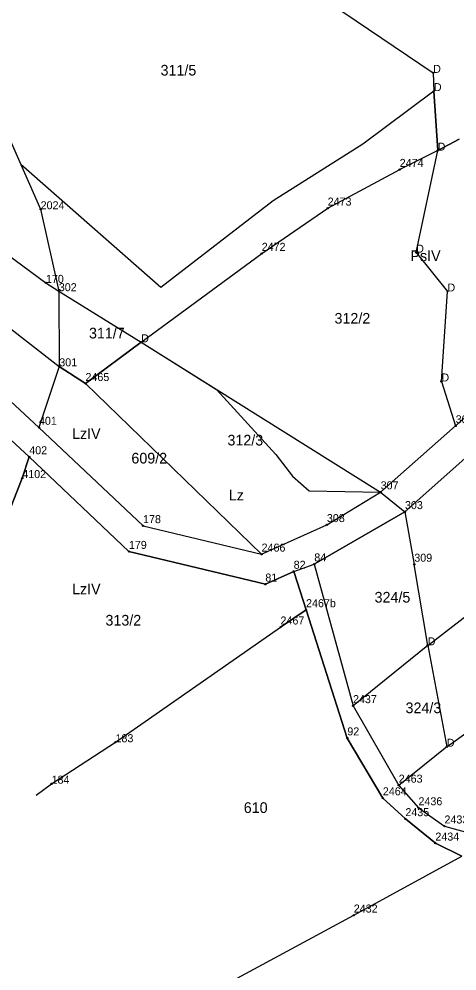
# Model space of a CAD drawing. Extents: x 7467189 to 7469366, y 5491487 to 5492734.
# Drawn here: x 7467655.3 to 7467716.9, y 5491813.8 to 5491947.6 of the extents above; entities that cross this region are included whole.
import ezdxf

# ---------------------------------------------------------------- set-up
doc = ezdxf.new("R2010")
doc.units = 0
for name, color, linetype in [('203-punkt graniczny', 7, 'Continuous'), ('203-punkt graniczny-Atr103', 7, 'Continuous'), ('209-oznaczenie konturu klasyfikacyjnego', 7, 'Continuous'), ('210-oznaczenie konturu użytku gruntowego', 7, 'Continuous'), ('211-numer działki ewidencyjnej', 7, 'Continuous'), ('217-kontur klasyfikacyjny', 7, 'Continuous'), ('218-kontur użytku gruntowego', 7, 'Continuous'), ('219-działka ewidencyjna', 7, 'Continuous')]:
    doc.layers.add(name, color=color, linetype=linetype)

# ---------------------------------------------------------------- blocks, each defined once
blk = doc.blocks.new('203')
blk.add_circle((0, 0), 0.09)

msp = doc.modelspace()

# ---------------------------------------------------------------- linework, layer by layer
at = {"layer": '217-kontur klasyfikacyjny'}
for points in [[(7467643.85, 5491953.77), (7467655.58, 5491927.15)], [(7467713.61, 5491937.44), (7467703.61, 5491929.97)], [(7467714.15, 5491929.08), (7467713.61, 5491937.44)], [(7467717.15, 5491930.69), (7467714.15, 5491929.08)], [(7467703.61, 5491929.97), (7467691.02, 5491922.04)], [(7467655.58, 5491927.15), (7467658.36, 5491920.84)], [(7467675.26, 5491909.83), (7467655.58, 5491927.15)], [(7467691.02, 5491922.04), (7467675.26, 5491909.83)], [(7467658.36, 5491920.84), (7467660.91, 5491909.33)], [(7467660.91, 5491909.33), (7467660.98, 5491898.77)], [(7467716.67, 5491890.39), (7467736.74, 5491908.19)], [(7467664.66, 5491896.34), (7467672.49, 5491902.15)], [(7467672.49, 5491902.15), (7467683.06, 5491895.54)], [(7467660.98, 5491898.77), (7467658.12, 5491890.18)], [(7467664.66, 5491896.34), (7467660.98, 5491898.77)], [(7467689.4, 5491872.36), (7467664.66, 5491896.34)], [(7467683.06, 5491895.54), (7467691.41, 5491886.39)], [(7467706.13, 5491881.11), (7467716.67, 5491890.39)], [(7467658.12, 5491890.18), (7467672.75, 5491876.36)], [(7467691.41, 5491886.39), (7467693.75, 5491883.34)], [(7467656.76, 5491886.05), (7467655.78, 5491883.07)], [(7467670.76, 5491872.75), (7467656.76, 5491886.05)], [(7467655.78, 5491883.07), (7467644.62, 5491854.62)], [(7467693.75, 5491883.34), (7467696.09, 5491881.3)], [(7467696.09, 5491881.3), (7467706.13, 5491881.11)], [(7467672.75, 5491876.36), (7467689.4, 5491872.36)], [(7467689.93, 5491868.15), (7467670.76, 5491872.75)], [(7467693.91, 5491869.96), (7467689.93, 5491868.15)], [(7467695.65, 5491864.56), (7467693.91, 5491869.96)], [(7467692.06, 5491862.13), (7467695.65, 5491864.56)], [(7467668.88, 5491845.96), (7467692.06, 5491862.13)], [(7467659.9, 5491840.13), (7467668.88, 5491845.96)], [(7467657.71, 5491838.52), (7467659.9, 5491840.13)]]:
    msp.add_lwpolyline(points, dxfattribs=at)
at = {"layer": '218-kontur użytku gruntowego'}
for points in [[(7467643.85, 5491953.77), (7467655.58, 5491927.15)], [(7467713.61, 5491937.44), (7467703.61, 5491929.97)], [(7467714.15, 5491929.08), (7467713.61, 5491937.44)], [(7467608.28, 5491936.44), (7467658.12, 5491890.18)], [(7467656.76, 5491886.05), (7467607.61, 5491931.54)], [(7467717.15, 5491930.69), (7467714.15, 5491929.08)], [(7467703.61, 5491929.97), (7467691.02, 5491922.04)], [(7467655.58, 5491927.15), (7467658.36, 5491920.84)], [(7467675.26, 5491909.83), (7467655.58, 5491927.15)], [(7467691.02, 5491922.04), (7467675.26, 5491909.83)], [(7467658.36, 5491920.84), (7467660.91, 5491909.33)], [(7467660.91, 5491909.33), (7467660.98, 5491898.77)], [(7467716.67, 5491890.39), (7467736.74, 5491908.19)], [(7467664.66, 5491896.34), (7467672.49, 5491902.15)], [(7467672.49, 5491902.15), (7467683.06, 5491895.54)], [(7467660.98, 5491898.77), (7467658.12, 5491890.18)], [(7467660.98, 5491898.77), (7467664.66, 5491896.34)], [(7467683.06, 5491895.54), (7467691.41, 5491886.39)], [(7467706.13, 5491881.11), (7467716.67, 5491890.39)], [(7467658.12, 5491890.18), (7467672.75, 5491876.36)], [(7467691.41, 5491886.39), (7467693.75, 5491883.34)], [(7467718.86, 5491886.6), (7467709.55, 5491878.34)], [(7467656.76, 5491886.05), (7467655.78, 5491883.07)], [(7467670.76, 5491872.75), (7467656.76, 5491886.05)], [(7467655.78, 5491883.07), (7467644.62, 5491854.62)], [(7467693.75, 5491883.34), (7467696.09, 5491881.3)], [(7467696.09, 5491881.3), (7467706.13, 5491881.11)], [(7467698.58, 5491876.52), (7467706.13, 5491881.11)], [(7467709.55, 5491878.34), (7467696.81, 5491870.98)], [(7467672.75, 5491876.36), (7467689.4, 5491872.36)], [(7467689.4, 5491872.36), (7467698.58, 5491876.52)], [(7467689.93, 5491868.15), (7467670.76, 5491872.75)], [(7467696.81, 5491870.98), (7467702.25, 5491851.07)], [(7467693.91, 5491869.96), (7467689.93, 5491868.15)], [(7467695.65, 5491864.56), (7467693.91, 5491869.96)], [(7467701.45, 5491846.54), (7467695.65, 5491864.56)], [(7467702.25, 5491851.07), (7467708.67, 5491839.9)], [(7467706.44, 5491838.12), (7467701.45, 5491846.54)], [(7467708.67, 5491839.9), (7467711.45, 5491836.72)], [(7467709.61, 5491835.19), (7467706.44, 5491838.12)], [(7467711.45, 5491836.72), (7467715.1, 5491834.17)], [(7467713.82, 5491831.77), (7467709.61, 5491835.19)], [(7467715.1, 5491834.17), (7467718.85, 5491833.15)], [(7467717.54, 5491829.96), (7467713.82, 5491831.77)]]:
    msp.add_lwpolyline(points, dxfattribs=at)
at = {"layer": '219-działka ewidencyjna'}
for points in [[(7467666.33, 5491971.9), (7467713.51, 5491940.01)], [(7467640.88, 5491960.5), (7467658.36, 5491920.84)], [(7467615.57, 5491942.65), (7467659.1, 5491910.5)], [(7467713.51, 5491940.01), (7467713.61, 5491937.44)], [(7467713.61, 5491937.44), (7467714.15, 5491929.08)], [(7467608.28, 5491936.44), (7467658.12, 5491890.18)], [(7467616.38, 5491933.43), (7467660.98, 5491898.77)], [(7467607.61, 5491931.54), (7467656.76, 5491886.05)], [(7467714.15, 5491929.08), (7467717.15, 5491930.69)], [(7467714.15, 5491929.08), (7467708.81, 5491926.41)], [(7467711.13, 5491914.75), (7467714.15, 5491929.08)], [(7467698.69, 5491920.98), (7467708.81, 5491926.41)], [(7467658.36, 5491920.84), (7467660.91, 5491909.33)], [(7467689.42, 5491914.62), (7467698.69, 5491920.98)], [(7467672.49, 5491902.15), (7467689.42, 5491914.62)], [(7467711.13, 5491914.75), (7467715.52, 5491909.29)], [(7467659.1, 5491910.5), (7467660.91, 5491909.33)], [(7467660.91, 5491909.33), (7467672.49, 5491902.15)], [(7467660.91, 5491909.33), (7467660.98, 5491898.77)], [(7467714.67, 5491896.65), (7467715.52, 5491909.29)], [(7467716.67, 5491890.39), (7467737.69, 5491909.03)], [(7467672.49, 5491902.15), (7467664.66, 5491896.34)], [(7467672.49, 5491902.15), (7467706.13, 5491881.11)], [(7467660.98, 5491898.77), (7467658.12, 5491890.18)], [(7467660.98, 5491898.77), (7467664.66, 5491896.34)], [(7467689.4, 5491872.36), (7467664.66, 5491896.34)], [(7467714.67, 5491896.65), (7467716.67, 5491890.39)], [(7467706.13, 5491881.11), (7467716.67, 5491890.39)], [(7467658.12, 5491890.18), (7467672.75, 5491876.36)], [(7467709.55, 5491878.34), (7467718.86, 5491886.6)], [(7467655.78, 5491883.07), (7467656.76, 5491886.05)], [(7467656.76, 5491886.05), (7467670.76, 5491872.75)], [(7467644.62, 5491854.62), (7467655.78, 5491883.07)], [(7467698.58, 5491876.52), (7467706.13, 5491881.11)], [(7467706.13, 5491881.11), (7467709.55, 5491878.34)], [(7467696.81, 5491870.98), (7467709.55, 5491878.34)], [(7467709.55, 5491878.34), (7467710.86, 5491870.94)], [(7467672.75, 5491876.36), (7467689.4, 5491872.36)], [(7467689.4, 5491872.36), (7467698.58, 5491876.52)], [(7467670.76, 5491872.75), (7467689.93, 5491868.15)], [(7467693.91, 5491869.96), (7467696.81, 5491870.98)], [(7467696.81, 5491870.98), (7467702.25, 5491851.07)], [(7467712.75, 5491859.57), (7467710.86, 5491870.94)], [(7467689.93, 5491868.15), (7467693.91, 5491869.96)], [(7467693.91, 5491869.96), (7467695.65, 5491864.56)], [(7467712.75, 5491859.57), (7467725.38, 5491869.31)], [(7467695.65, 5491864.56), (7467692.06, 5491862.13)], [(7467695.65, 5491864.56), (7467701.45, 5491846.54)], [(7467668.88, 5491845.96), (7467692.06, 5491862.13)], [(7467712.75, 5491859.57), (7467702.25, 5491851.07)], [(7467712.75, 5491859.57), (7467715.43, 5491845.32)], [(7467715.43, 5491845.32), (7467727.85, 5491854.25)], [(7467702.25, 5491851.07), (7467708.67, 5491839.9)], [(7467701.45, 5491846.54), (7467706.44, 5491838.12)], [(7467659.9, 5491840.13), (7467668.88, 5491845.96)], [(7467715.43, 5491845.32), (7467708.67, 5491839.9)], [(7467657.71, 5491838.52), (7467659.9, 5491840.13)], [(7467708.67, 5491839.9), (7467711.45, 5491836.72)], [(7467706.44, 5491838.12), (7467709.61, 5491835.19)], [(7467711.45, 5491836.72), (7467715.1, 5491834.17)], [(7467709.61, 5491835.19), (7467713.82, 5491831.77)], [(7467715.1, 5491834.17), (7467718.85, 5491833.15)], [(7467713.82, 5491831.77), (7467717.54, 5491829.96)], [(7467702.36, 5491821.65), (7467717.54, 5491829.96)], [(7467684.85, 5491812.19), (7467702.36, 5491821.65)]]:
    msp.add_lwpolyline(points, dxfattribs=at)

# ---------------------------------------------------------------- block references
at = {"layer": '203-punkt graniczny'}
for p in [(7467713.51, 5491940.01), (7467713.61, 5491937.44), (7467714.15, 5491929.08), (7467708.81, 5491926.41), (7467658.36, 5491920.84), (7467698.69, 5491920.98), (7467689.42, 5491914.62), (7467711.13, 5491914.75), (7467659.1, 5491910.5), (7467660.91, 5491909.33), (7467715.52, 5491909.29), (7467672.49, 5491902.15), (7467660.98, 5491898.77), (7467664.66, 5491896.34), (7467714.67, 5491896.65), (7467716.67, 5491890.39), (7467658.12, 5491890.18), (7467656.76, 5491886.05), (7467655.78, 5491883.07), (7467706.13, 5491881.11), (7467709.55, 5491878.34), (7467672.75, 5491876.36), (7467698.58, 5491876.52), (7467670.76, 5491872.75), (7467689.4, 5491872.36), (7467696.81, 5491870.98), (7467710.86, 5491870.94), (7467693.91, 5491869.96), (7467689.93, 5491868.15), (7467695.65, 5491864.56), (7467692.06, 5491862.13), (7467712.75, 5491859.57), (7467702.25, 5491851.07), (7467701.45, 5491846.54), (7467668.88, 5491845.96), (7467715.43, 5491845.32), (7467659.9, 5491840.13), (7467708.67, 5491839.9), (7467706.44, 5491838.12), (7467711.45, 5491836.72), (7467709.61, 5491835.19), (7467715.1, 5491834.17), (7467713.82, 5491831.77), (7467702.36, 5491821.65)]:
    msp.add_blockref('203', p, dxfattribs=at)

# ---------------------------------------------------------------- texts
at = {"layer": '203-punkt graniczny-Atr103'}
for s, height, p in [('D', 1.12, (7467713.51, 5491940.01)), ('D', 1.12, (7467713.61, 5491937.44)), ('D', 1.12, (7467714.15, 5491929.08)), ('2474', 1.125, (7467708.81, 5491926.79)), ('2473', 1.125, (7467698.69, 5491921.36)), ('2024', 1.125, (7467658.36, 5491920.84)), ('2472', 1.125, (7467689.42, 5491915)), ('D', 1.12, (7467711.13, 5491914.75)), ('170', 1.125, (7467659.1, 5491910.5)), ('302', 1.125, (7467660.91, 5491909.33)), ('D', 1.12, (7467715.52, 5491909.29)), ('D', 1.12, (7467672.49, 5491902.15)), ('301', 1.125, (7467660.98, 5491898.77)), ('2465', 1.125, (7467664.66, 5491896.71)), ('D', 1.12, (7467714.67, 5491896.65)), ('401', 1.125, (7467658.12, 5491890.56)), ('306', 1.125, (7467716.67, 5491890.77)), ('402', 1.125, (7467656.76, 5491886.42)), ('4102', 1.125, (7467655.78, 5491883.07)), ('307', 1.125, (7467706.13, 5491881.49)), ('303', 1.125, (7467709.55, 5491878.71)), ('178', 1.125, (7467672.75, 5491876.74)), ('308', 1.125, (7467698.58, 5491876.89)), ('179', 1.125, (7467670.76, 5491873.12)), ('2466', 1.125, (7467689.4, 5491872.74)), ('84', 1.125, (7467696.81, 5491871.36)), ('309', 1.125, (7467710.86, 5491871.32)), ('82', 1.125, (7467693.91, 5491870.33)), ('81', 1.125, (7467689.93, 5491868.53)), ('2467b', 1.125, (7467695.65, 5491864.93)), ('2467', 1.125, (7467692.06, 5491862.5)), ('D', 1.12, (7467712.75, 5491859.57)), ('2437', 1.125, (7467702.25, 5491851.45)), ('92', 1.125, (7467701.45, 5491846.92)), ('183', 1.125, (7467668.88, 5491845.96)), ('D', 1.12, (7467715.43, 5491845.32)), ('184', 1.125, (7467659.9, 5491840.13)), ('2463', 1.125, (7467708.67, 5491840.28)), ('2464', 1.125, (7467706.44, 5491838.5)), ('2436', 1.125, (7467711.45, 5491837.1)), ('2435', 1.125, (7467709.61, 5491835.57)), ('2433', 1.125, (7467715.1, 5491834.54)), ('2434', 1.125, (7467713.82, 5491832.14)), ('2432', 1.125, (7467702.36, 5491822.03))]:
    msp.add_text(s, height=height, dxfattribs=at).set_placement(p)
at = {"layer": '209-oznaczenie konturu klasyfikacyjnego'}
for s, p in [('PsIV', (7467710.32, 5491913.55)), ('LzIV', (7467662.77, 5491888.57)), ('LzIV', (7467662.77, 5491866.74))]:
    msp.add_text(s, height=1.5, dxfattribs=at).set_placement(p)
at = {"layer": '210-oznaczenie konturu użytku gruntowego'}
for s, p in [('Ps', (7467710.32, 5491913.55)), ('Lz', (7467684.8, 5491879.94))]:
    msp.add_text(s, height=1.5, dxfattribs=at).set_placement(p)
at = {"layer": '211-numer działki ewidencyjnej'}
for s, p in [('311/5', (7467675.21, 5491939.63)), ('312/2', (7467699.65, 5491904.77)), ('311/7', (7467665.15, 5491902.69)), ('312/3', (7467684.61, 5491887.65)), ('609/2', (7467671.11, 5491885.12)), ('324/5', (7467705.28, 5491865.58)), ('313/2', (7467667.47, 5491862.35)), ('324/3', (7467709.63, 5491850.04)), ('610', (7467686.9, 5491836.02))]:
    msp.add_text(s, height=1.5, dxfattribs=at).set_placement(p)

doc.saveas('drawing.dxf')
